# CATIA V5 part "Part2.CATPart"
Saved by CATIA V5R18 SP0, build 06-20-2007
Part number: Part2
Bounding box of the stored display mesh (mm): x 0 to 20, y -69.015 to 69.015, z 7.835 to 66.136
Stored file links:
  D:\Shriniwas\v5_r19\c16_CAT_v5r19\c16_Part\Slide curve Joint\Part2.CATPart
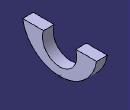
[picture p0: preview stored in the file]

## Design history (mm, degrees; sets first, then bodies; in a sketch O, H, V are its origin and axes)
Body1 (main body)
  Sketch1 on yz-plane, origin (0, 0, 0), H (0, 1, 0), V (0, 0, 1)
    arc A1 centre (0, 77.8354) radius 70 from (-69.0153, 66.1355) to (69.0153, 66.1355) ccw
    point P1 (0, 77.8354)
    point P2 (-69.0153, 66.1355)
    point P3 (69.0153, 66.1355)
    arc A2 centre (0, 55) radius 32 from (-30, 66.1355) to (30, 66.1355) ccw
    point P4 (0, 55)
    point P5 (-30, 66.1355)
    point P6 (30, 66.1355)
    line L1 (30, 66.1355) -> (69.0153, 66.1355)
    point P7 (69.0153, 66.1355)
    line L2 (-30, 66.1355) -> (-69.0153, 66.1355)
    point P8 (-69.0153, 66.1355)
    reference intersected line E1 through (0, 0) direction (-1, 0) from xy-plane
    reference intersected line E3 through (0, 0) direction (0, 1) from zx-plane
    radius A1 = 70
    radius A2 = 32
    distance P6 P7 = 39.0153
    distance P6 E3 = 30
    distance P4 H = 55
    coincidence: P1 V, P4 V, P7 P3, P8 A1, P2 P8, L2 L1, E3 P1, P2 L1, P3 L1, P5 L1, P6 L2
    horizontal: L1 H, L2 H, E1 H
    vertical: E3 V
    perpendicularity: E3 L1
  Pad1: profile Sketch1, direction (1, 0, 0), length 20
  Point1: type OnCurve, Support edge [face of Pad1 from Sketch1.A1 | end face of Pad1], Ratio 0.5
  Sketch2 on yz-plane, origin (0, 0, 0), H (0, 1, 0), V (0, 0, 1)
    line L1 (0, 81.1355) -> (0, 51.1355)
    point P1 (0, 81.1355)
    reference projected line E1 (69.0153, 66.1355) -> (30, 66.1355) from edge [face of Pad1 from Sketch1.L1 | end face of Pad1]
    length L1 = 30
    distance E1 P1 = 15
    coincidence: P1 V
    vertical: L1 V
